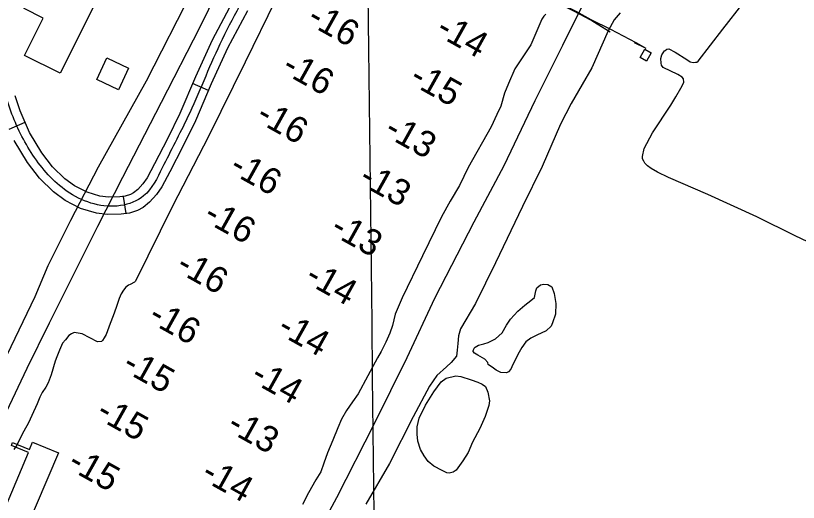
# Model space of a CAD drawing. Extents: x 3683402 to 3721514, y 487807 to 513565.
# Drawn here: x 3697569 to 3698925, y 495778 to 496621 of the extents above; entities that cross this region are included whole.
import ezdxf

# ---------------------------------------------------------------- set-up
doc = ezdxf.new("R2010")
doc.units = 0
for name, color, linetype in [('V-BLDG-OTLN', 7, 'Continuous'), ('V-CHAN-DOCK', 7, 'Continuous'), ('V-GRID-MAJR', 7, 'Continuous'), ('V-LEVE-TOET', 7, 'Continuous'), ('V-ROAD-CNTR', 7, 'Continuous'), ('V-TOPO-SHOR', 7, 'Continuous'), ('V-TOPO-SPOT', 7, 'Continuous'), ('V-UTIL-LINE', 7, 'Continuous'), ('V-WETL-SWMP', 7, 'Continuous')]:
    doc.layers.add(name, color=color, linetype=linetype)

msp = doc.modelspace()

# ---------------------------------------------------------------- linework, layer by layer
at = {"layer": 'V-BLDG-OTLN'}
for points in [[(3697721.7120000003, 496672.976), (3697646.344, 496521.43200000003), (3697584.539, 496552.168), (3697616.793, 496617.02400000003), (3697583.531, 496633.566), (3697601.81, 496670.318), (3697635.637, 496653.493), (3697660.473, 496703.434)], [(3698658.828, 496563.264), (3698670.143, 496557.00200000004), (3698662.078, 496542.42600000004), (3698650.761, 496548.689)], [(3697727.119, 496547.853), (3697764.642, 496530.052), (3697747.0130000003, 496492.887), (3697709.488, 496510.688)]]:
    msp.add_lwpolyline(points, close=True, dxfattribs=at)
at = {"layer": 'V-CHAN-DOCK'}
msp.add_lwpolyline([(3697563.451, 495881.909), (3697593.071, 495869.777), (3697598.343, 495882.618), (3697643.306, 495864.155), (3697584.431, 495726.314), (3697540.552, 495744.898), (3697591.293, 495864.905), (3697561.681, 495876.666), (3697563.451, 495881.909)], dxfattribs=at)
at = {"layer": 'V-GRID-MAJR'}
msp.add_spline([(3698217.897, 493344.793), (3698148.292, 499402.231), (3698078.651, 505462.753), (3698009.0100000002, 511523.288), (3698008.975, 511526.359)], degree=3, dxfattribs=at)
at = {"layer": 'V-LEVE-TOET'}
for points in [[(3696897.431, 494628.849), (3696982.151, 494790.981), (3697049.1040000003, 494917.963), (3697132.33, 495082.489), (3697217.951, 495248.50800000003), (3697296.926, 495407.15), (3697388.349, 495600.854), (3697443.424, 495715.53), (3697511.665, 495851.728), (3697553.258, 495935.19800000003), (3697589.182, 496010.829), (3697627.957, 496089.413), (3697668.149, 496169.956), (3697711.615, 496256.849), (3697754.642, 496341.315), (3697821.546, 496471.199), (3697887.973, 496600.58900000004), (3697949.613, 496726.994)], [(3697875.222, 496665.202), (3697795.2600000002, 496507.50800000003), (3697711.761, 496358.46), (3697664.026, 496266.655), (3697624.768, 496188.063), (3697602.002, 496134.438), (3697553.954, 496032.949)], [(3698062.843, 495670.95300000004), (3698125.291, 495786.802), (3698190.835, 495915.034), (3698247.145, 496029.351), (3698295.127, 496131.669), (3698363.443, 496264.218), (3698415.312, 496361.387), (3698468.802, 496474.232), (3698516.901, 496569.912), (3698557.187, 496651.705)], [(3698616.4420000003, 496625.722), (3698605.75, 496613.68), (3698595.647, 496595.00800000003), (3698567.384, 496530.499), (3698550.347, 496501.749), (3698531.489, 496468.69800000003), (3698513.145, 496433.286), (3698481.252, 496359.70300000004), (3698446.903, 496290.819), (3698400.255, 496193.267), (3698365.466, 496122.47500000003), (3698339.682, 496078.874), (3698336.1, 496066.956), (3698334.912, 496053.659), (3698333.697, 496041.782), (3698332.934, 496031.337), (3698323.636, 496020.74100000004), (3698315.239, 496013.00800000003), (3698298.906, 495998.021), (3698285.9590000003, 495979.3), (3698257.489, 495926.64), (3698216.722, 495845.313), (3698175.754, 495775.362)]]:
    msp.add_lwpolyline(points, dxfattribs=at)
at = {"layer": 'V-ROAD-CNTR'}
for p, q in [((3697903.048154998, 496491.5419908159), (3697875.465210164, 496503.33896722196)), ((3697557.9658451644, 496424.3331252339), (3697585.34279041, 496436.60210069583)), ((3697760.639439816, 496278.5024168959), (3697756.000449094, 496308.14135761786))]:
    msp.add_line(p, q, dxfattribs=at)
for points in [[(3697944.11207287, 496643.64668660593), (3697909.390142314, 496578.3748171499), (3697880.4172002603, 496514.915944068), (3697853.27725454, 496451.46007097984), (3697832.0012970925, 496407.878158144), (3697809.7163416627, 496364.518244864), (3697796.5983678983, 496340.4592929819), (3697789.32738244, 496329.98431393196), (3697780.448400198, 496320.003333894), (3697773.3194144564, 496314.3483452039), (3697768.2214246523, 496311.6503506), (3697758.9524431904, 496308.603356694), (3697749.4774621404, 496307.1203596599), (3697729.6695017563, 496306.8703601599), (3697715.115530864, 496308.6893565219), (3697692.6425758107, 496315.1713435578), (3697670.7516195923, 496326.55432079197), (3697654.0326530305, 496338.7922963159), (3697632.6196958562, 496359.52825484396), (3697614.344732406, 496383.73020643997), (3697593.2487745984, 496418.9601359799), (3697576.630807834, 496456.04206181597), (3697568.461824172, 496482.3840091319)], [(3697970.58201993, 496629.5267148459), (3697936.30208849, 496565.0888437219), (3697907.85714538, 496502.785968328), (3697880.565199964, 496438.9740959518), (3697858.825243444, 496394.44018502), (3697836.2302886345, 496350.478272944), (3697822.164316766, 496324.6793245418), (3697812.941335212, 496311.3943511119), (3697801.13235883, 496298.11937766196), (3697789.7973815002, 496289.126395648), (3697780.005401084, 496283.94440601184), (3697766.00242909, 496279.3414152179), (3697751.999457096, 496277.1504196), (3697727.991505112, 496276.846420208), (3697709.061542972, 496279.21341547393), (3697681.454598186, 496287.17539954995), (3697654.8796513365, 496300.99437191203), (3697634.646691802, 496315.80434229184), (3697610.0797409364, 496339.59429471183), (3697589.4327822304, 496366.9362400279), (3697566.598827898, 496405.0721637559)]]:
    msp.add_lwpolyline(points, dxfattribs=at)
msp.add_spline([(3698242.8074754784, 497214.69754450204), (3698198.9605631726, 497122.5717287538), (3698125.692709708, 496977.4830189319), (3698061.7578375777, 496833.81130627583), (3697991.99197711, 496701.36257117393), (3697922.8461154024, 496571.731830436), (3697866.921227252, 496445.21708346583), (3697822.9733151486, 496357.498258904), (3697790.790379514, 496309.061355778), (3697750.7384596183, 496292.13538962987), (3697662.815635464, 496313.77434635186), (3697601.8887573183, 496375.33322323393), (3697562.571835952, 496450.7340724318), (3697548.1478648, 496507.0399598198), (3697546.0478690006, 496618.03373783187), (3697517.8029254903, 496700.9355720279), (3697443.22307465, 496741.82949023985), (3697348.477264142, 496783.05440778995), (3697323.700313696, 496822.7993283), (3697356.206248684, 496937.228099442), (3697412.855135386, 497036.39990109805), (3697463.0620349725, 497134.95570398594), (3697492.5649759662, 497209.64955459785), (3697506.889947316, 497243.3384872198), (3697525.3149104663, 497264.467444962)], degree=3, dxfattribs=at)
at = {"layer": 'V-TOPO-SHOR'}
for points in [[(3698852.8880000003, 496272.543), (3698768.322, 496311.639), (3698700.171, 496340.585), (3698681.059, 496350.299), (3698670.1240000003, 496356.677), (3698663.8680000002, 496360.818), (3698658.756, 496365.753), (3698657.148, 496369.202), (3698655.1410000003, 496373.42100000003), (3698655.074, 496377.284), (3698657.927, 496390.864), (3698672.134, 496418.17), (3698703.761, 496465.882), (3698712.782, 496480.343), (3698721.404, 496495.57), (3698724.771, 496501.814), (3698726.631, 496506.099), (3698725.7600000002, 496511.493), (3698723.776, 496514.55100000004), (3698715.9590000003, 496519.439), (3698690.625, 496531.36100000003), (3698687.852, 496535.17600000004), (3698687.0160000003, 496538.641), (3698686.488, 496546.749), (3698688.698, 496552.971), (3698693.2120000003, 496560.00800000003), (3698694.356, 496560.803), (3698697.021, 496563.168), (3698700.492, 496563.617), (3698711.807, 496557.63), (3698731.739, 496545.228), (3698737.608, 496541.07800000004), (3698742.6520000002, 496540.007), (3698746.896, 496540.47000000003), (3698748.827, 496540.503), (3698751.119, 496542.09), (3698794.203, 496597.73600000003), (3698864.5, 496688.262)], [(3698019.282, 496648.65), (3697966.538, 496540.353), (3697903.66, 496413.273), (3697840.693, 496291.231), (3697776.701, 496161.418), (3697775.177, 496159.841), (3697767.503, 496155.44200000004), (3697764.81, 496154.232), (3697759.836, 496150.656), (3697755.662, 496145.544), (3697751.889, 496139.662), (3697748.551, 496131.077), (3697743.392, 496115.869), (3697737.8340000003, 496101.43), (3697733.035, 496087.778), (3697728.216, 496075.292), (3697725.613, 496069.043), (3697722.615, 496063.178), (3697719.203, 496058.852), (3697718.069, 496057.281), (3697717.688, 496056.88800000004), (3697711.1070000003, 496056.384), (3697684.125, 496069.862), (3697670.1210000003, 496072.717), (3697665.5130000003, 496070.311), (3697661.296, 496067.52400000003), (3697655.234, 496059.663), (3697650.298, 496053.76300000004), (3697645.08, 496042.042), (3697640.247, 496030.33), (3697637.67, 496022.531), (3697630.33, 495999.147), (3697625.534, 495985.495), (3697621.407, 495977.67), (3697614.985, 495968.255), (3697610.858, 495960.43), (3697606.025, 495948.717), (3697597.075, 495928.792), (3697591.093, 495916.283), (3697583.214, 495901.414), (3697576.085, 495888.11100000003), (3697570.844, 495877.55100000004), (3697565.943, 495869.713)], [(3698487.566, 496623.568), (3698483.752, 496620.012), (3698480.734, 496615.308), (3698461.364, 496570.77900000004), (3698433.808, 496528.819), (3698423.015, 496503.434), (3698415.9390000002, 496487.032), (3698409.748, 496464.44), (3698402.637, 496449.973), (3698392.551, 496428.477), (3698352.707, 496358.00800000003), (3698337.752, 496326.735), (3698321.563, 496299.705), (3698306.535, 496272.694), (3698273.609, 496205.446), (3698238.85, 496132.353), (3698226.554, 496104.228), (3698221.86, 496084.766), (3698217.054, 496071.503), (3698210.353, 496055.879), (3698202.115, 496039.456), (3698196.1070000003, 496028.49700000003), (3698162.319, 495966.27), (3698152.4820000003, 495952.532), (3698142.287, 495937.23600000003), (3698133.247, 495922.347), (3698127.312, 495907.126), (3698118.77, 495886.044), (3698109.083, 495863.78), (3698103.193, 495846.233), (3698097.639, 495831.408), (3698088.974, 495817.30100000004), (3698076.5810000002, 495794.601), (3698066.079, 495774.647)], [(3698941.542, 496229.5), (3698919.325, 496239.93), (3698852.8880000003, 496272.543)], [(3698387.046, 496020.276), (3698381.561, 496026.326), (3698369.9250000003, 496033.031), (3698363.715, 496036.76300000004), (3698361.7490000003, 496039.417), (3698361.3370000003, 496040.945), (3698363.559, 496045.591), (3698365.0670000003, 496047.15400000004), (3698370.77, 496050.326), (3698379.943, 496052.792), (3698387.58, 496055.231), (3698400.532, 496061.22000000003), (3698411.866, 496071.787), (3698419.306, 496085.358), (3698426.4250000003, 496095.468), (3698438.856, 496109.12700000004), (3698450.958, 496119.70900000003), (3698461.5700000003, 496127.575), (3698467.6180000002, 496133.05700000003), (3698470.102, 496144.623), (3698471.933, 496149.646), (3698478.364, 496155.135), (3698484.111, 496156.005), (3698491.0330000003, 496155.358), (3698497.628, 496151.635), (3698502.059, 496139.81), (3698505.052, 496122.582), (3698504.224, 496104.136), (3698499.106, 496089.454), (3698496.522, 496083.647), (3698488.217, 496075.43700000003), (3698471.839, 496067.851), (3698461.562, 496062.68), (3698452.848, 496055.99700000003), (3698446.1, 496046.663), (3698441.252, 496038.514), (3698430.1070000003, 496017.196), (3698426.802, 496008.691), (3698422.6520000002, 496004.39400000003), (3698419.2320000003, 496002.411), (3698409.615, 496003.395), (3698401.484, 496007.091), (3698396.811, 496010.849), (3698387.873, 496016.836), (3698387.046, 496020.276)]]:
    msp.add_lwpolyline(points, dxfattribs=at)
at = {"layer": 'V-UTIL-LINE'}
msp.add_line((3698640.318, 496574.485), (3698659.323, 496565.583), dxfattribs=at)
for points in [[(3698502.68, 496646.356), (3698535.323, 496629.558), (3698556.028, 496618.44800000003), (3698568.693, 496611.536), (3698599.131, 496593.04000000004)], [(3698507.7060000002, 496644.201), (3698539.616, 496628.757), (3698565.556, 496614.325), (3698599.718, 496597.804), (3698643.31, 496574.379), (3698660.9760000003, 496564.641)]]:
    msp.add_lwpolyline(points, dxfattribs=at)
at = {"layer": 'V-WETL-SWMP'}
msp.add_lwpolyline([(3698319.759, 495829.01), (3698315.907, 495829.71), (3698307.7770000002, 495833.407), (3698293.432, 495841.218), (3698283.6920000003, 495849.11100000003), (3698276.613, 495858.586), (3698270.275, 495869.61100000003), (3698265.789, 495884.50800000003), (3698264.427, 495896.38800000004), (3698264.588, 495909.063), (3698268.163, 495924.102), (3698278.903, 495946.563), (3698293.469, 495969.86), (3698306.223, 495986.981), (3698314.56, 495993.272), (3698331.767, 495997.41500000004), (3698340.233, 495996.412), (3698358, 495990.581), (3698369.591, 495986.56200000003), (3698376.946, 495983.235), (3698382.785, 495978.73), (3698386.793, 495969.201), (3698390.1350000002, 495953.89900000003), (3698388.741, 495945.811), (3698382.54, 495927.26900000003), (3698373.315, 495905.987), (3698360.292, 495882.333), (3698352.918, 495864.923), (3698343.9620000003, 495850.173), (3698331.955, 495834.217), (3698327.026, 495830.674)], close=True, dxfattribs=at)

# ---------------------------------------------------------------- texts
at = {"layer": 'V-TOPO-SPOT'}
for s, p in [('-16', (3698071.595183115, 496608.167178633)), ('-14', (3698294.7262386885, 496588.8562290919)), ('-16', (3698027.8751831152, 496523.847178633)), ('-15', (3698248.9862386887, 496504.7062290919)), ('-16', (3697983.075183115, 496439.437178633)), ('-13', (3698205.249445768, 496414.4639793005)), ('-16', (3697937.065183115, 496350.627178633)), ('-13', (3698161.259445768, 496330.9539793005)), ('-16', (3697892.1451831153, 496266.7971786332)), ('-13', (3698111.789445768, 496244.23397930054)), ('-16', (3697844.525183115, 496179.557178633)), ('-14', (3698067.9262386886, 496160.1162290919)), ('-16', (3697796.495183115, 496092.137178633)), ('-14', (3698019.9562386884, 496071.8762290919)), ('-15', (3697751.4462386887, 496007.8662290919)), ('-14', (3697973.7362386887, 495988.9162290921)), ('-15', (3697705.9262386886, 495925.46622909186)), ('-13', (3697932.679445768, 495903.4439793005)), ('-15', (3697656.6462386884, 495837.8062290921)), ('-14', (3697887.9362386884, 495819.15622909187))]:
    msp.add_text(s, height=45, rotation=330.79328332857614, dxfattribs=at).set_placement(p)

doc.saveas('drawing.dxf')
